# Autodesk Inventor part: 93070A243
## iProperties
Created: 2010-11
Part Number: 93070A243
Document SubType Name: Modeling
Designer: Administrator
Density: 7.85 g/cm^3
Material: Steel
Mass: 31.4252 g
Surface Area: 22.6747 cm^2
Volume: 4.00321 cm^3
Translation Standard: STEP AP203
FileName: 93070A243.step
PreProcessor: SolidWorks 2003314
PostProcessor: Build: 236a, Release: 2009 RTM - Date: Fri 02/22/2008
Sent Units: MM
Uncertainty: 1e-05
Author: Administrator
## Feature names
1. Base1
